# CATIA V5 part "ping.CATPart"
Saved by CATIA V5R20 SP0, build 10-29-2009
Part number: Part1
Material "Grey Blue": density 7860 kg/m3, Young's modulus 2e+11 Pa, Poisson ratio 0.266
Bounding box of the stored display mesh (mm): x -25 to 25, y -25 to 25, z 0 to 110
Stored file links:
  I:\180212721马可\ping.CATPart
  G:\catia v20\win_b64\startup\materials\Catalog.CATMaterial
  G:\catia v20\win_b64\startup\materials\green_env_512x512.jpg
  G:\catia v20\win_b64\startup\materials\wall_of_bricks.jpg
  G:\catia v20\win_b64\startup\materials\road.jpg
  G:\catia v20\win_b64\startup\materials\roof2.jpg
  G:\catia v20\win_b64\startup\materials\wire.png
  G:\catia v20\win_b64\startup\materials\alcantara.jpg
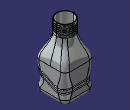
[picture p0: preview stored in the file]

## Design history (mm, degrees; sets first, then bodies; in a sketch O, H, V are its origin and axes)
Set1
  Sketch1 on xy-plane, origin (0, 0, 0), H (1, 0, 0), V (0, 1, 0)
    line L1 (25, 25) -> (25, -25)
    line L2 (25, -25) -> (-25, -25)
    line L3 (-25, -25) -> (-25, 25)
    line L4 (-25, 25) -> (25, 25)
    distance L2 L4 = 50
    distance L1 L3 = 50
    vertical: L1 V, L3 V
    horizontal: L2 H, L4 H
    equidistance: L1 L3 O, L2 L4 O
  Sketch2 on face of Pad1 from Sketch1.L1, origin (25, 0, 0), H (0, 1, 0), V (0, 0, 1)
    spline S1 through (-41.0208, 19.1785) (-23.8194, 29.3752) (5.3146, 19.1785) (39.2526, 27.8303)
  Extrude1: Element1 Sketch2, Lim1 100, Lim2 100
  MultiSel1: CommonCtxFeats ({extract ExtractElem face of Fillet1}; {extract ExtractElem face of Pad1 from Sketch1.L4}; {extract ExtractElem face of Fillet1}; {extract ExtractElem face of Pad1 from Sketch1.L3}; {extract ExtractElem face of Fillet1}; {extract ExtractElem face of Pad1 from Sketch1.L2}; {extract ExtractElem face of Fillet1}; {extract ExtractElem face of Pad1 from Sketch1.L1})
  Sketch3 on face of Pad1 from Sketch1.L3, origin (-25, 0, 0), H (0, -1, 0), V (0, 0, 1)
    spline S1 through (-29.1754, 26.7043) (-15.4565, 22.3207) (12.3331, 33.3675) (30.625, 35.121)
  Extrude2: Element1 Sketch3, Lim1 100, Lim2 100
  MultiSel2: CommonCtxFeats ({extract ExtractElem face of Pad1 from Sketch1.L3}; {extract ExtractElem face of Fillet1}; {extract ExtractElem face of Pad1 from Sketch1.L2}; {extract ExtractElem face of Fillet1}; {extract ExtractElem face of Pad1 from Sketch1.L1}; {extract ExtractElem face of Fillet1}; {extract ExtractElem face of Pad1 from Sketch1.L4}; {extract ExtractElem face of Fillet1})
  Join1: Elements ({intersect ToIntersect1 {extract ExtractElem face of Pad1 from Sketch1.L1}, ToIntersect2 Extrude2}; {intersect ToIntersect1 {extract ExtractElem face of Fillet1}, ToIntersect2 Extrude2}; {intersect ToIntersect1 {extract ExtractElem face of Pad1 from Sketch1.L4}, ToIntersect2 Extrude2}; {intersect ToIntersect1 {extract ExtractElem face of Fillet1}, ToIntersect2 Extrude2}; {intersect ToIntersect1 {extract ExtractElem face of Pad1 from Sketch1.L3}, ToIntersect2 Extrude2}; {intersect ToIntersect1 {extract ExtractElem face of Fillet1}, ToIntersect2 Extrude2}; {intersect ToIntersect1 {extract ExtractElem face of Pad1 from Sketch1.L2}, ToIntersect2 Extrude2}; {intersect ToIntersect1 {extract ExtractElem face of Fillet1}, ToIntersect2 Extrude2})
  Join2: Elements ({intersect ToIntersect1 {extract ExtractElem face of Pad1 from Sketch1.L1}, ToIntersect2 Extrude1}; {intersect ToIntersect1 {extract ExtractElem face of Fillet1}, ToIntersect2 Extrude1}; {intersect ToIntersect1 {extract ExtractElem face of Pad1 from Sketch1.L4}, ToIntersect2 Extrude1}; {intersect ToIntersect1 {extract ExtractElem face of Fillet1}, ToIntersect2 Extrude1}; {intersect ToIntersect1 {extract ExtractElem face of Pad1 from Sketch1.L3}, ToIntersect2 Extrude1}; {intersect ToIntersect1 {extract ExtractElem face of Fillet1}, ToIntersect2 Extrude1}; {intersect ToIntersect1 {extract ExtractElem face of Pad1 from Sketch1.L2}, ToIntersect2 Extrude1}; {intersect ToIntersect1 {extract ExtractElem face of Fillet1}, ToIntersect2 Extrude1})
  Plane1: type Normal, Curve Join1, RefPoint vertex [face of MultiSel2 | face of MultiSel2]
  Sketch4 on Plane1, origin (0, 7.2514, -1.4258), H (-1, 0, 0), V (0, 0.1929, 0.9812)
    circle A1 centre (-24.9405, 24.7394) radius 1
    radius A1 = 1
  Plane2: type Normal, Curve Join2, RefPoint vertex [face of MultiSel1 | face of MultiSel1]
  Sketch5 on Plane2, origin (0, 10.2539, -1.3853), H (-1, 0, 0), V (0, 0.1339, 0.991)
    circle A1 centre (-24.8669, 18.9887) radius 1
    radius A1 = 1
Body1 (main body), material "Grey Blue"
  Pad1: profile Sketch1, direction (0, 0, 1), length 50
  Fillet1: on edge [face of Pad1 from Sketch1.L2 | face of Pad1 from Sketch1.L3]; edge [face of Pad1 from Sketch1.L1 | face of Pad1 from Sketch1.L2]; edge [face of Pad1 from Sketch1.L3 | face of Pad1 from Sketch1.L4]; edge [face of Pad1 from Sketch1.L4 | face of Pad1 from Sketch1.L1]
  Fillet2: radius 8, on start face of Pad1
  Plane3: type Offset, RefPlane end face of Pad1, Offset 40, reversed
  Sketch6 on Plane3, origin (0, 0, 90), H (1, 0, 0), V (0, -1, 0)
    circle A1 centre (0, 0) radius 15
    radius A1 = 15
  Pad2: profile Sketch6, direction (0, 0, -1), length -20
  Sketch7 on end face of Pad1, origin (0, 0, 50), H (1, 0, 0), V (0, 1, 0)
    point P1 (25, 0)
    distance P1 V = 25
    coincidence: P1 H
  Sketch8 on start face of Pad2, origin (0, 0, 90), H (1, 0, 0), V (0, -1, 0)
  Sketch9 on start face of Pad2, origin (0, 0, 90), H (1, 0, 0), V (0, -1, 0)
  Sketch10 on start face of Pad2, origin (0, 0, 90), H (1, 0, 0), V (0, -1, 0)
    point P1 (15, 0)
    distance P1 V = 15
    distance P1 H = 0
  Loft1: solid, Sections ({boundary Boundary {extract ExtractElem end face of Pad1}}; {boundary Boundary {extract ExtractElem start face of Pad2}}), StartFace end face of Pad1, EndFace start face of Pad2
  Slot1: profile Sketch4, centre curve Join1
  Slot2: profile Sketch5, centre curve Join2
  Shell1: IntOffset 1, Face end face of Pad2, ExtOffset 0
  Plane4: type Offset, RefPlane Plane3, Offset -2
  Sketch11 on Plane4, origin (0, 0, 92), H (1, 0, 0), V (0, -1, 0)
    point P1 (15, 0)
    distance P1 V = 15
    distance P1 H = 0
  Helix1: Direction Z axis, RefPoint Sketch11, Pitch 3, Height 16, TaperAngle 0
  Point1: type OnCurve, Support Helix1, Length 5.262
  Line1: type PtDir, RefPoint Sketch11, Direction (1, 0, 0), Start 0, End 10
  Connect1: Curve1 Line1, Point1 vertex of Line1, Tension1 1, Curve2 Helix1, Point2 Point1, Tension2 1
  Line2: type PtDir, RefPoint vertex of Helix1, Direction (0, 1, 0), Start 0, End -10
  Point2: type OnCurve, Support Connect1, Length 500.359
  Connect2: Curve1 Line2, Point1 vertex of Line2, Tension1 1, Curve2 Connect1, Point2 Point2, Tension2 1
  Plane5: type Normal, Curve Connect2, RefPoint {point type OnCurve, Support Connect2, Ratio 0}
  Sketch12 on Plane5, origin (0, 2.9904, 0), H (-1, 0, 0), V (0, 0, 1)
    circle A1 centre (7.5041, 108.0117) radius 0.5
    radius A1 = 0.5
  Rib1: profile Sketch12, centre curve Connect2
  Body2
    Sketch13 on Plane3, origin (0, 0, 90), H (1, 0, 0), V (0, -1, 0)
      circle A1 centre (0, 0) radius 14
      radius A1 = 14
    Pad3: profile Sketch13, direction (0, 0, -1), length -30
  Remove1: tool Body2
  Body3
  Remove2: tool Body3
  Body4
  Remove3: tool Body4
